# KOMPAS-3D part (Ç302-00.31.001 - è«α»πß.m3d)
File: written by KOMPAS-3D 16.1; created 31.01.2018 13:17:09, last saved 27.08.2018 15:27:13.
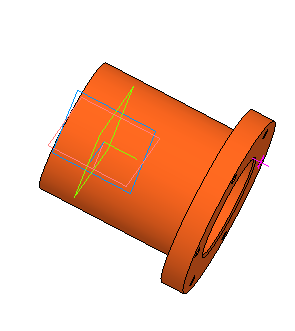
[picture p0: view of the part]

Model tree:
1. Эскиз:1
2. Операция вращения:1
     Угол 1 = 360
3. Условное изображение резьбы:1  (labels: M80x3)
     Длина резьбы = 20; Шаг резьбы = 3; Номинальный диаметр резьбы = 80
4. Подгонка:1
5. Эскиз:2
6. Вырезать элемент выдавливания:1
     Расстояние 1 = 9
7. Фаска:1
     Угол = 45; Длина 1 = 1; Длина 2 = 1
8. Эскиз:3
9. Операция выдавливания:1
     Расстояние 1 = 10; Расстояние 2 = 14
10. Эскиз:5
11. Отверстие:1
     Глубина выреза = 20; Диаметр отверстия = 6; Угол конуса торца = 118; Координата Y = 47
12. Массив по концентрической сетке:1  (with: Отверстие:1, Эскиз:5)  (6 pattern instances)
     Геометрический массив = 5; Шаг 2 = 360
13. Фаска:3
     Угол = 45; Длина 1 = 1; Длина 2 = 1
14. Фаска:4  (labels: Полипропилен  ГОСТ 26996-86)
     Угол = 45; Длина 1 = 1; Длина 2 = 1

Referenced files in C:\Program Files\ASCON\KOMPAS-3D V16\Sys\Thread\: cil0_8724-2002 fine.xml
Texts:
  Линейный размер с обрывом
